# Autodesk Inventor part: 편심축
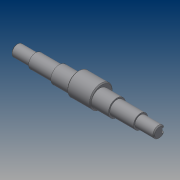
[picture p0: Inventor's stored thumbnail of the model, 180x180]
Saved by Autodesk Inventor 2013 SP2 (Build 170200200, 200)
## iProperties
Created: 2014-12
Part Number: 편심축
Material: Generic
Document SubType Name: Modeling
Designer: CADB302
Density: 1 g/cm^3
Author: CADB302
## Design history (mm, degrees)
sketch "스케치1"
  geometry: L1 (-75.5, 0)-(75.5, 0); L2 (-75.5, 0)-(-75.5, 6); L3 (-75.5, 6)-(-55.5, 6); L4 (-55.5, 6)-(-55.5, 7.5); L5 (-55.5, 7.5)-(-30.5, 7.5); L6 (-30.5, 7.5)-(-30.5, 9); L7 (30.5, 9)-(30.5, 7.5); L8 (30.5, 7.5)-(55.5, 7.5); L9 (55.5, 7.5)-(55.5, 6); L10 (55.5, 6)-(75.5, 6); L11 (75.5, 6)-(75.5, 0); L12 (-30.5, 9)-(30.5, 9); L13 (12.5, 2)-(-12.5, 2); L14 (-12.5, 2)-(-12.5, 14); L15 (-12.5, 14)-(12.5, 14); L16 (12.5, 14)-(12.5, 2); L17 (-75.5, 6)-(-61.5, 6); L18 (-61.5, 6)-(-61.5, 3); L19 (-61.5, 3)-(-75.5, 3); L20 (-75.5, 3)-(-75.5, 6); L21 (75.5, 6)-(61.5, 6); L22 (61.5, 6)-(61.5, 3); L23 (61.5, 3)-(75.5, 3); L24 (75.5, 3)-(75.5, 6); 2 further points
  constraints: 48 end point, 13 parallel, 6 perpendicular, 4 horizontal, 1 coincident, 1 collinear, 1 midpoint
  dimensions: "d0" = 151 distance of L1.start L1.end; "d7" = 12 diameter of L10 L1; "d8" = 12 diameter of L3 L1; "d9" = 15 diameter of L5 L1; "d10" = 15 diameter of L8 L1; "d13" = 18 diameter of L12 L1; "d14" = 20 distance of L2.end L3.end; "d15" = 25 distance of L4.end L5.end; "d16" = 20 distance of L9.end L10.end; "d17" = 25 distance of L7.end L8.end; "d18" = 4 diameter of L13 L1; "d19" = 12 distance of L13.end L14.end; "d20" = 18 distance between parallel lines of L14 L6; "d21" = 18 distance between parallel lines of L7 L16; "d22" = 14 distance of L2.end L17.end; "d23" = 3 distance of L17.end L18.end; "d24" = 14 distance of L10.end L21.end; "d25" = 3 distance of L21.end L22.end
revolve "회전1" stored, may be unused: angle "d26" = 90 deg
revolve "회전2" stored, may be unused: angle "d27" = 90 deg
extrude "돌출1" cut sketch "스케치1" stored distance "d28" = 5; taper "d29" = 0 deg
extrude "돌출2" cut sketch "스케치1" stored distance "d30" = 5; taper "d31" = 0 deg
fillet "모깎기1" dims "d32" = 2.5
chamfer "모따기1" distance "d33" = 1; stored, may be unused: second distance "d34" = 2, angle "d35" = 45 deg
node "솔리드1"
